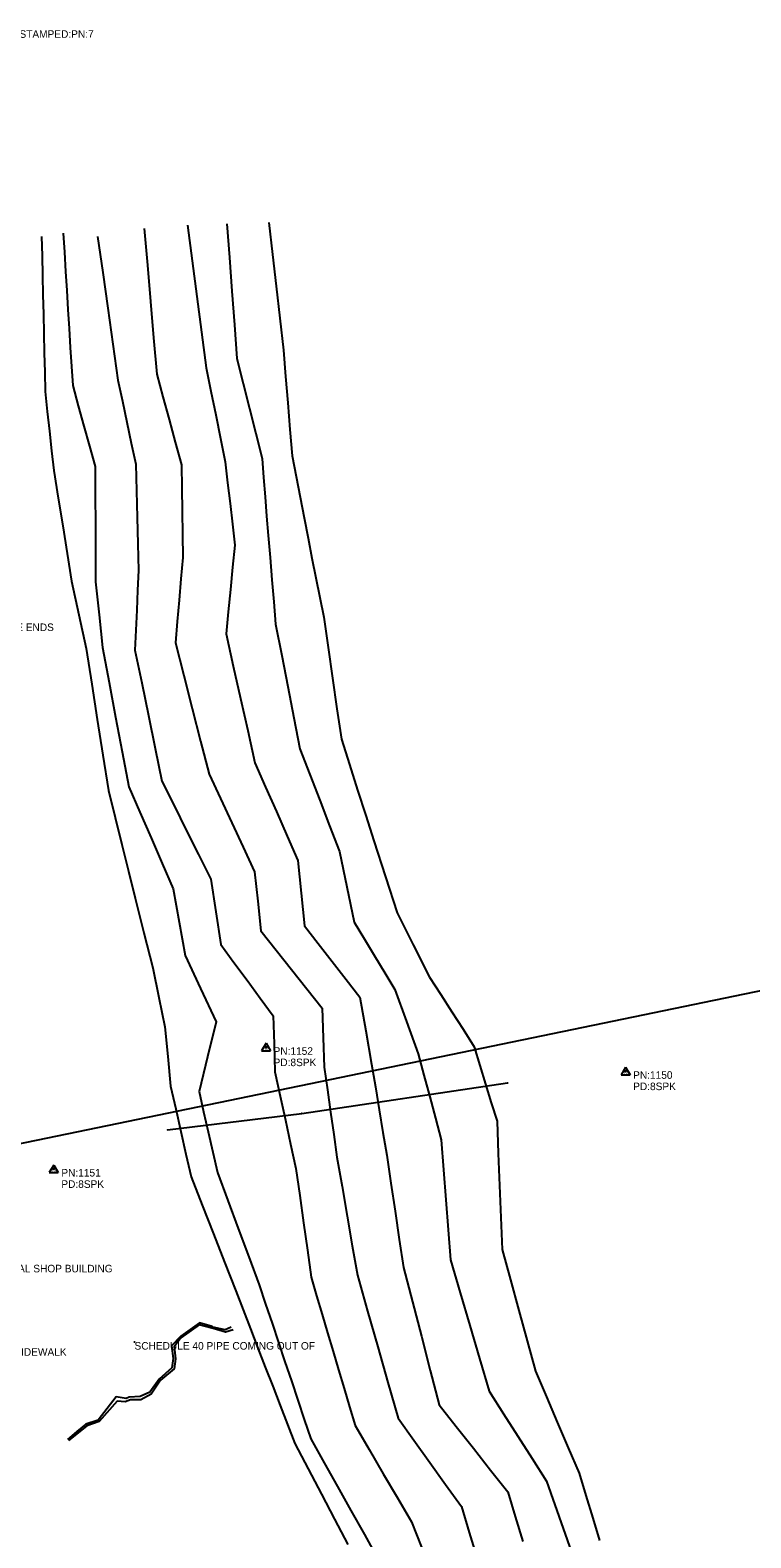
# Model space of a CAD drawing. Extents: x 1734049 to 1769984, y 344166 to 379510.
# Drawn here: x 1736361 to 1736837, y 378046 to 379043 of the extents above; entities that cross this region are included whole.
import ezdxf

# ---------------------------------------------------------------- set-up
doc = ezdxf.new("R2010")
doc.units = 0
for name, color, linetype in [('S_BASELINE', 7, 'Continuous'), ('S_BUILDING_ANNOT', 7, 'Continuous'), ('S_DITCHLINE', 7, 'Continuous'), ('S_MSC_PT_SYM', 7, 'Continuous'), ('S_PRIMARY_CTL_ANNOT', 7, 'Continuous'), ('S_SECONDARY_CTL', 7, 'Continuous'), ('S_SECONDARY_CTL_ANNOT', 7, 'Continuous'), ('S_STREAM', 7, 'Continuous'), ('S_SURVEY_TEXT_ANNOT', 7, 'Continuous'), ('S_UTL_PT_SYM', 7, 'Continuous'), ('S_WATER_UTILITIES', 7, 'Continuous')]:
    doc.layers.add(name, color=color, linetype=linetype)

msp = doc.modelspace()

# ---------------------------------------------------------------- linework, layer by layer
at = {"layer": 'S_BASELINE'}
msp.add_line((1736142.34, 378263.18), (1737017.96, 378443.92), dxfattribs=at)
at = {"layer": 'S_DITCHLINE'}
for points in [[(1736493.79, 378185.32), (1736489.88, 378183.59), (1736481.69, 378185.45), (1736481.23, 378185.93), (1736472.89, 378188.29), (1736460.57, 378179.57), (1736454.43, 378173.1), (1736455.61, 378164.74), (1736454.62, 378158.55), (1736446.36, 378150.94), (1736440.14, 378142.53), (1736433.72, 378139.64), (1736426.55, 378139.13), (1736424.44, 378138.2), (1736417.93, 378139.26), (1736406.02, 378123.98), (1736397.75, 378121.25), (1736391.77, 378116.37), (1736385.66, 378111.25)], [(1736495.13, 378183.74), (1736490.12, 378182.06), (1736481.91, 378184.62), (1736481.06, 378184.73), (1736472.74, 378186.89), (1736460.68, 378178.36), (1736456.2, 378172.35), (1736456.97, 378164.44), (1736456.26, 378157.94), (1736447.13, 378150.41), (1736440.99, 378141.07), (1736434.21, 378137.47), (1736427.31, 378137.36), (1736423.75, 378136.17), (1736418.58, 378136.52), (1736406.64, 378122.97), (1736398.36, 378120.27), (1736392.81, 378115.63), (1736386.35, 378110.49)]]:
    msp.add_lwpolyline(points, dxfattribs=at)
at = {"layer": 'S_MSC_PT_SYM'}
msp.add_lwpolyline([(1736429.99, 378175.58), (1736429.99, 378175.63), (1736429.99, 378175.58), (1736429.94, 378175.58), (1736429.99, 378175.58), (1736429.99, 378175.53), (1736429.99, 378175.58), (1736430.04, 378175.58)], dxfattribs=at)
at = {"layer": 'S_SECONDARY_CTL'}
for p, q in [((1736516.88, 378373.1), (1736513.87, 378368.14)), ((1736516.88, 378373.1), (1736519.82, 378368.14)), ((1736513.87, 378368.14), (1736519.82, 378368.14)), ((1736754.51, 378357.24), (1736751.5, 378352.29)), ((1736751.5, 378352.29), (1736757.46, 378352.29)), ((1736754.51, 378357.24), (1736757.46, 378352.29)), ((1736376.62, 378292.62), (1736373.61, 378287.67)), ((1736376.62, 378292.62), (1736379.57, 378287.67)), ((1736373.61, 378287.67), (1736379.57, 378287.67))]:
    msp.add_line(p, q, dxfattribs=at)
for centre, radius in [((1736516.88, 378370.49), 0.311), ((1736516.88, 378370.49), 0.183), ((1736516.88, 378370.49), 0.103), ((1736754.51, 378354.63), 0.311), ((1736754.51, 378354.63), 0.183), ((1736754.51, 378354.63), 0.103), ((1736376.62, 378290.01), 0.311), ((1736376.62, 378290.01), 0.183), ((1736376.62, 378290.01), 0.103)]:
    msp.add_circle(centre, radius, dxfattribs=at)
at = {"layer": 'S_STREAM'}
for points in [[(1736382.81, 378908.64), (1736383.6, 378896.05), (1736384.39, 378883.47), (1736385.18, 378870.88), (1736385.97, 378858.3), (1736386.76, 378845.71), (1736387.55, 378833.13), (1736388.34, 378820.54), (1736389.13, 378807.96), (1736392.83, 378794.57), (1736396.53, 378781.19), (1736400.24, 378767.8), (1736403.94, 378754.42), (1736404.02, 378735.37), (1736404.1, 378716.32), (1736404.17, 378697.27), (1736404.25, 378678.22), (1736406.54, 378656.48), (1736408.83, 378634.74), (1736413.15, 378611.73), (1736417.48, 378588.72), (1736421.81, 378565.71), (1736426.14, 378542.69), (1736433.51, 378525.81), (1736440.88, 378508.94), (1736448.24, 378492.06), (1736455.61, 378475.18), (1736459.52, 378453.18), (1736463.42, 378431.18), (1736473.68, 378409.24), (1736483.93, 378387.29), (1736478.29, 378364.25), (1736472.65, 378341.21), (1736475.68, 378327.84), (1736478.71, 378314.48), (1736481.75, 378301.11), (1736484.78, 378287.74), (1736491.66, 378269.17), (1736498.54, 378250.6), (1736505.42, 378232.03), (1736512.3, 378213.46), (1736516.57, 378200.74), (1736520.84, 378188.01), (1736525.11, 378175.29), (1736529.39, 378162.57), (1736533.66, 378149.85), (1736537.93, 378137.13), (1736542.2, 378124.41), (1736546.48, 378111.68), (1736555.33, 378095.84), (1736564.18, 378080), (1736573.03, 378064.15), (1736581.88, 378048.31), (1736591.46, 378031.02)], [(1736405.6, 378906.55), (1736408.95, 378882.81), (1736412.3, 378859.08), (1736415.64, 378835.34), (1736418.99, 378811.6), (1736421.93, 378797.68), (1736424.88, 378783.75), (1736427.82, 378769.82), (1736430.76, 378755.89), (1736431.23, 378738.36), (1736431.7, 378720.82), (1736432.17, 378703.28), (1736432.63, 378685.75), (1736432.05, 378672.58), (1736431.47, 378659.41), (1736430.88, 378646.24), (1736430.3, 378633.07), (1736434.73, 378611.4), (1736439.16, 378589.72), (1736443.59, 378568.05), (1736448.02, 378546.38), (1736456.1, 378530.21), (1736464.18, 378514.04), (1736472.26, 378497.88), (1736480.34, 378481.71), (1736483.7, 378460.02), (1736487.06, 378438.32), (1736495.72, 378426.53), (1736504.38, 378414.74), (1736513.04, 378402.94), (1736521.7, 378391.15), (1736522.2, 378372.66), (1736522.71, 378354.18), (1736526.2, 378338.23), (1736529.68, 378322.29), (1736533.17, 378306.35), (1736536.65, 378290.4), (1736539.17, 378272.4), (1736541.69, 378254.39), (1736544.21, 378236.39), (1736546.73, 378218.38), (1736550.35, 378206.14), (1736553.98, 378193.9), (1736557.61, 378181.66), (1736561.23, 378169.41), (1736564.86, 378157.17), (1736568.49, 378144.93), (1736572.11, 378132.69), (1736575.74, 378120.45), (1736585.07, 378104.5), (1736594.39, 378088.56), (1736603.72, 378072.61), (1736613.05, 378056.67), (1736619.68, 378039.88)], [(1736436.43, 378911.68), (1736438.5, 378887.62), (1736440.56, 378863.56), (1736442.62, 378839.51), (1736444.69, 378815.45), (1736448.76, 378800.45), (1736452.84, 378785.45), (1736456.92, 378770.45), (1736460.99, 378755.45), (1736461.22, 378740.14), (1736461.44, 378724.83), (1736461.67, 378709.52), (1736461.89, 378694.21), (1736460.66, 378680.13), (1736459.43, 378666.06), (1736458.2, 378651.98), (1736456.97, 378637.91), (1736462.53, 378616.21), (1736468.1, 378594.52), (1736473.67, 378572.83), (1736479.24, 378551.14), (1736486.77, 378534.99), (1736494.3, 378518.84), (1736501.83, 378502.7), (1736509.36, 378486.55), (1736511.39, 378467.05), (1736513.43, 378447.54), (1736523.59, 378434.73), (1736533.74, 378421.92), (1736543.9, 378409.11), (1736554.06, 378396.29), (1736554.72, 378376.78), (1736555.39, 378357.26), (1736557.48, 378342.43), (1736559.58, 378327.59), (1736561.67, 378312.76), (1736563.76, 378297.92), (1736567.14, 378278.37), (1736570.51, 378258.81), (1736573.88, 378239.25), (1736577.25, 378219.7), (1736583.99, 378196.09), (1736590.72, 378172.48), (1736597.46, 378148.87), (1736604.2, 378125.27), (1736614.66, 378110.65), (1736625.12, 378096.03), (1736635.58, 378081.41), (1736646.04, 378066.8), (1736651.18, 378049.6), (1736656.33, 378032.41)], [(1736464.97, 378914.01), (1736468.05, 378890.45), (1736471.13, 378866.89), (1736474.22, 378843.32), (1736477.3, 378819.76), (1736480.47, 378804.19), (1736483.63, 378788.63), (1736486.79, 378773.06), (1736489.96, 378757.49), (1736491.53, 378743.73), (1736493.11, 378729.98), (1736494.68, 378716.22), (1736496.26, 378702.46), (1736494.82, 378687.78), (1736493.39, 378673.09), (1736491.95, 378658.41), (1736490.52, 378643.72), (1736495.27, 378622.44), (1736500.03, 378601.16), (1736504.79, 378579.88), (1736509.55, 378558.6), (1736516.64, 378542.45), (1736523.74, 378526.29), (1736530.83, 378510.14), (1736537.93, 378493.98), (1736540.07, 378472.38), (1736542.21, 378450.78), (1736551.4, 378438.98), (1736560.59, 378427.18), (1736569.78, 378415.38), (1736578.97, 378403.58), (1736582.79, 378381.39), (1736586.61, 378359.2), (1736589.13, 378344.21), (1736591.66, 378329.21), (1736594.19, 378314.21), (1736596.71, 378299.22), (1736599.47, 378280.63), (1736602.23, 378262.04), (1736604.98, 378243.45), (1736607.74, 378224.86), (1736613.64, 378202.16), (1736619.54, 378179.46), (1736625.43, 378156.77), (1736631.33, 378134.07), (1736642.65, 378119.7), (1736653.98, 378105.34), (1736665.3, 378090.98), (1736676.62, 378076.61), (1736681.58, 378060.15), (1736686.54, 378043.69)], [(1736491.05, 378914.78), (1736492.69, 378892.57), (1736494.34, 378870.36), (1736495.98, 378848.14), (1736497.63, 378825.93), (1736501.8, 378809.4), (1736505.98, 378792.88), (1736510.16, 378776.35), (1736514.34, 378759.82), (1736515.33, 378747.08), (1736516.31, 378734.34), (1736517.3, 378721.59), (1736518.29, 378708.85), (1736519.53, 378694.19), (1736520.77, 378679.52), (1736522.01, 378664.86), (1736523.25, 378650.19), (1736527.27, 378629.58), (1736531.29, 378608.97), (1736535.3, 378588.36), (1736539.32, 378567.75), (1736545.85, 378550.77), (1736552.39, 378533.78), (1736558.93, 378516.79), (1736565.46, 378499.8), (1736570.3, 378476.46), (1736575.14, 378453.13), (1736581.87, 378442.01), (1736588.59, 378430.89), (1736595.31, 378419.76), (1736602.03, 378408.64), (1736609.78, 378387.41), (1736617.53, 378366.19), (1736621.29, 378351.98), (1736625.04, 378337.77), (1736628.8, 378323.57), (1736632.56, 378309.36), (1736634.13, 378289.5), (1736635.7, 378269.64), (1736637.27, 378249.78), (1736638.85, 378229.92), (1736645.22, 378208.2), (1736651.6, 378186.47), (1736657.98, 378164.75), (1736664.36, 378143.03), (1736673.82, 378128.19), (1736683.28, 378113.35), (1736692.74, 378098.51), (1736702.2, 378083.67), (1736707.75, 378068.02), (1736713.3, 378052.38), (1736718.85, 378036.73)], [(1736518.72, 378915.79), (1736521.13, 378894.7), (1736523.53, 378873.6), (1736525.93, 378852.5), (1736528.33, 378831.4), (1736529.78, 378813.93), (1736531.23, 378796.46), (1736532.67, 378778.98), (1736534.12, 378761.51), (1736536.75, 378747.87), (1736539.38, 378734.23), (1736542.01, 378720.59), (1736544.65, 378706.95), (1736547.23, 378693.92), (1736549.82, 378680.9), (1736552.4, 378667.88), (1736554.99, 378654.85), (1736557.92, 378634.68), (1736560.84, 378614.5), (1736563.77, 378594.32), (1736566.7, 378574.14), (1736572.06, 378557.33), (1736577.41, 378540.52), (1736582.77, 378523.71), (1736588.12, 378506.9), (1736595.82, 378483.14), (1736603.51, 378459.37), (1736614.23, 378438.14), (1736624.95, 378416.92), (1736632.33, 378405.39), (1736639.71, 378393.86), (1736647.08, 378382.34), (1736654.46, 378370.81), (1736658.24, 378358.49), (1736662.01, 378346.16), (1736665.79, 378333.84), (1736669.57, 378321.52), (1736670.4, 378300.34), (1736671.23, 378279.17), (1736672.06, 378257.99), (1736672.89, 378236.82), (1736678.4, 378216.68), (1736683.92, 378196.54), (1736689.43, 378176.39), (1736694.95, 378156.25), (1736702.15, 378139.4), (1736709.34, 378122.55), (1736716.54, 378105.7), (1736723.74, 378088.85), (1736728.25, 378074.03), (1736732.77, 378059.2), (1736737.29, 378044.38)], [(1736368.61, 378906.46), (1736368.9, 378893.64), (1736369.18, 378880.82), (1736369.47, 378868.01), (1736369.76, 378855.19), (1736370.05, 378842.38), (1736370.34, 378829.56), (1736370.63, 378816.75), (1736370.92, 378803.93), (1736372.33, 378790.87), (1736373.75, 378777.81), (1736375.17, 378764.75), (1736376.59, 378751.69), (1736379.54, 378733.41), (1736382.5, 378715.14), (1736385.46, 378696.86), (1736388.41, 378678.58), (1736393.2, 378656.34), (1736397.99, 378634.1), (1736401.69, 378610.61), (1736405.39, 378587.12), (1736409.09, 378563.63), (1736412.8, 378540.13), (1736417.18, 378522.38), (1736421.56, 378504.62), (1736425.94, 378486.87), (1736430.32, 378469.11), (1736436.19, 378446.1), (1736442.07, 378423.08), (1736446, 378403.48), (1736449.94, 378383.89), (1736451.89, 378364.34), (1736453.84, 378344.8), (1736457.22, 378329.83), (1736460.61, 378314.86), (1736464, 378299.89), (1736467.38, 378284.92), (1736474.75, 378266.08), (1736482.11, 378247.23), (1736489.48, 378228.39), (1736496.85, 378209.54), (1736501.74, 378196.91), (1736506.63, 378184.28), (1736511.53, 378171.64), (1736516.42, 378159.01), (1736521.31, 378146.37), (1736526.2, 378133.74), (1736531.09, 378121.11), (1736535.99, 378108.47), (1736544.74, 378091.79), (1736553.49, 378075.12), (1736562.24, 378058.44), (1736570.99, 378041.76)]]:
    msp.add_lwpolyline(points, dxfattribs=at)
at = {"layer": 'S_UTL_PT_SYM'}
for points in [[(1736676.53, 378346.9), (1736676.53, 378346.95), (1736676.53, 378346.9), (1736676.48, 378346.9), (1736676.53, 378346.9), (1736676.53, 378346.85), (1736676.53, 378346.9), (1736676.58, 378346.9)], [(1736540.47, 378326.72), (1736540.47, 378326.77), (1736540.47, 378326.72), (1736540.42, 378326.72), (1736540.47, 378326.72), (1736540.47, 378326.67), (1736540.47, 378326.72), (1736540.52, 378326.72)], [(1736451.72, 378315.88), (1736451.72, 378315.93), (1736451.72, 378315.88), (1736451.67, 378315.88), (1736451.72, 378315.88), (1736451.72, 378315.83), (1736451.72, 378315.88), (1736451.77, 378315.88)]]:
    msp.add_lwpolyline(points, dxfattribs=at)
at = {"layer": 'S_WATER_UTILITIES'}
for p, q in [((1736540.47, 378326.72), (1736676.53, 378346.9)), ((1736451.72, 378315.88), (1736540.47, 378326.72))]:
    msp.add_line(p, q, dxfattribs=at)

# ---------------------------------------------------------------- texts
at = {"layer": 'S_BUILDING_ANNOT'}
msp.add_text('METAL SHOP BUILDING', height=5, dxfattribs=at).set_placement((1736338.93, 378221.67))
msp.add_text('METAL SHOP BUILDING', height=5, dxfattribs=at).set_placement((1736338.93, 378221.67))
at = {"layer": 'S_PRIMARY_CTL_ANNOT'}
msp.add_text('PD:STD ARDOT MON STAMPED:PN:7', height=5, dxfattribs=at).set_placement((1736284.86, 379037.85))
at = {"layer": 'S_SECONDARY_CTL'}
for p in [(1736515.67, 378368.47), (1736753.31, 378352.62), (1736375.42, 378288)]:
    msp.add_text('TV', height=1.5, rotation=360, dxfattribs=at).set_placement(p)
at = {"layer": 'S_SECONDARY_CTL_ANNOT'}
for s, p in [('PN:1152', (1736521.88, 378365.49)), ('PD:8SPK', (1736521.88, 378357.99)), ('PN:1150', (1736759.51, 378349.63)), ('PD:8SPK', (1736759.51, 378342.13)), ('PN:1151', (1736381.62, 378285.01)), ('PD:8SPK', (1736381.62, 378277.51))]:
    msp.add_text(s, height=5, dxfattribs=at).set_placement(p)
at = {"layer": 'S_SURVEY_TEXT_ANNOT'}
for s, p in [('DITCHLINE ENDS', (1736320.95, 378645.65)), ('CONC SIDEWALK', (1736329, 378166.54)), ('SCHEDULE 40 PIPE COMING OUT OF ', (1736429.99, 378170.58))]:
    msp.add_text(s, height=5, dxfattribs=at).set_placement(p)

doc.saveas('drawing.dxf')
